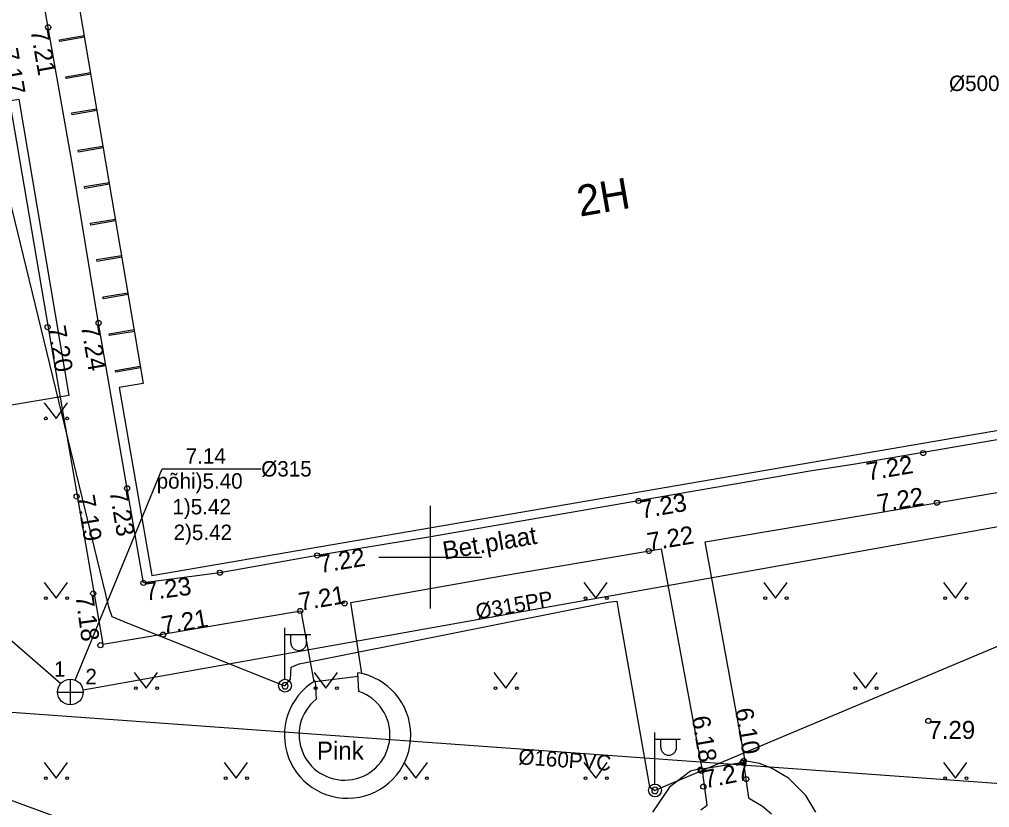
# Model space of a CAD drawing. Extents: x 473307 to 473719, y 6532843 to 6533381.
# Drawn here: x 473584.01 to 473621.77, y 6532940.25 to 6532970.93 of the extents above; entities that cross this region are included whole.
import ezdxf

# ---------------------------------------------------------------- set-up
doc = ezdxf.new("R2010")
doc.units = 0
for name, color, linetype in [('AED', 7, 'Continuous'), ('Default', 7, 'Continuous'), ('HALJASTUS', 7, 'Continuous'), ('HOONE', 7, 'Continuous'), ('HOONEDET', 7, 'Continuous'), ('KKAEV_NR', 7, 'Continuous'), ('KORGUS', 7, 'Continuous'), ('KTRASS', 7, 'Continuous'), ('KTRASS_TEKST', 7, 'Continuous'), ('MPKAABEL', 7, 'Continuous'), ('POST', 7, 'Continuous'), ('RAJATIS', 7, 'Continuous'), ('SKKAEV', 7, 'Continuous'), ('SKKAEV_NR', 7, 'Continuous'), ('SKTRASS', 7, 'Continuous'), ('SKTRASS_TEKST', 7, 'Continuous'), ('TEE', 7, 'Continuous'), ('VORK', 7, 'Continuous'), ('VTRASS', 7, 'Continuous')]:
    doc.layers.add(name, color=color, linetype=linetype)

# ---------------------------------------------------------------- blocks, each defined once
blk = doc.blocks.new('MURU')
at = {"layer": 'Default'}
for p, q in [((-0.927, 1.213), (0, 0)), ((0, 0), (0.891, 1.213))]:
    blk.add_line(p, q, dxfattribs=at)
for centre in [(-0.802, 0), (0.856, 0)]:
    blk.add_circle(centre, 0.11, dxfattribs=at)
blk = doc.blocks.new('MEPOST')
at = {"layer": 'Default'}
blk.add_circle((0, 0), 0.5, dxfattribs=at)
for start, end in [(0, 180), (180, 0)]:
    blk.add_arc((0, 0), 0.25, start, end, dxfattribs=at)
blk = doc.blocks.new('VAPOST')
at = {"layer": 'Default'}
for p, q in [((0, 0.5), (0, 4.5)), ((0, 4), (2, 4)), ((0.453, 3.358), (0.453, 4)), ((1.679, 3.358), (1.679, 4))]:
    blk.add_line(p, q, dxfattribs=at)
blk.add_arc((1.066, 3.358), 0.613, 180, 0, dxfattribs=at)
blk = doc.blocks.new('KAKAEV')
at = {"layer": 'Default'}
for p, q in [((0, -1), (0, 1)), ((-1, 0), (1, 0))]:
    blk.add_line(p, q, dxfattribs=at)
blk.add_circle((0, 0), 1, dxfattribs=at)
blk = doc.blocks.new('VKORIS')
at = {"layer": 'Default'}
for p, q in [((0, 4), (0, -4)), ((-4, 0), (4, 0))]:
    blk.add_line(p, q, dxfattribs=at)

msp = doc.modelspace()

# ---------------------------------------------------------------- linework, layer by layer
at = {"layer": 'AED'}
msp.add_lwpolyline([(473550.051, 6532959.211), (473554.174, 6532956.453), (473573.719, 6532945.513), (473580.254, 6532941.8), (473591.86, 6532937.524), (473605.919, 6532932.298), (473608.286, 6532931.42), (473621.231, 6532928.229), (473637.541, 6532925.082), (473652.528, 6532925.143), (473654.3, 6532926.84), (473651.933, 6532941.676), (473648.983, 6532959.55), (473630.652, 6532956.493)], dxfattribs=at)
at = {"layer": 'HOONE'}
msp.add_lwpolyline([(473585.831, 6533013.369), (473574.881, 6533011.486), (473566.132, 6533009.962), (473540.511, 6533005.576), (473543.395, 6532988.91), (473585.455, 6532976.623), (473588.828, 6532956.753), (473587.886, 6532956.595), (473589.164, 6532949.286), (473629.221, 6532956.166), (473626.335, 6532972.834), (473619.836, 6532974.765), (473602.305, 6532979.874), (473597.625, 6532979.18), (473590.334, 6532981.418), (473586.157, 6533005.917), (473587.084, 6533006.076)], close=True, dxfattribs=at)
at = {"layer": 'HOONEDET'}
for points in [[(473586.54, 6532970.231), (473585.585, 6532970.069), (473585.573, 6532970.138), (473586.529, 6532970.3)], [(473586.785, 6532968.791), (473585.831, 6532968.629), (473585.819, 6532968.698), (473586.773, 6532968.86)], [(473587.024, 6532967.381), (473586.061, 6532967.218), (473586.049, 6532967.287), (473587.012, 6532967.45)], [(473587.27, 6532965.93), (473586.307, 6532965.767), (473586.295, 6532965.836), (473587.259, 6532965.999)], [(473587.511, 6532964.514), (473586.548, 6532964.351), (473586.536, 6532964.42), (473587.499, 6532964.583)], [(473587.753, 6532963.086), (473586.793, 6532962.923), (473586.781, 6532962.992), (473587.742, 6532963.155)], [(473587.993, 6532961.674), (473587.03, 6532961.511), (473587.018, 6532961.58), (473587.981, 6532961.743)], [(473588.24, 6532960.22), (473587.274, 6532960.056), (473587.262, 6532960.125), (473588.228, 6532960.289)], [(473588.483, 6532958.786), (473587.509, 6532958.621), (473587.497, 6532958.69), (473588.471, 6532958.855)], [(473588.725, 6532957.363), (473587.759, 6532957.199), (473587.747, 6532957.268), (473588.713, 6532957.432)]]:
    msp.add_lwpolyline(points, dxfattribs=at)
at = {"layer": 'KORGUS'}
for centre in [(473585.127, 6532970.62), (473587.089, 6532959.111), (473585.106, 6532958.952), (473619.184, 6532954.05), (473588.198, 6532952.676), (473586.235, 6532952.361), (473608.106, 6532952.185), (473619.718, 6532952.115), (473595.6, 6532950.065), (473608.504, 6532950.235), (473591.811, 6532949.391), (473588.835, 6532948.995), (473586.881, 6532948.583), (473596.663, 6532948.199), (473594.939, 6532947.905), (473589.602, 6532946.984), (473587.16, 6532946.57), (473619.382, 6532943.624), (473612.195, 6532942.07), (473610.517, 6532941.729), (473610.556, 6532941.68), (473612.155, 6532942), (473612.295, 6532941.358), (473610.625, 6532941.068)]:
    msp.add_circle(centre, 0.1, dxfattribs=at)
at = {"layer": 'KTRASS'}
msp.add_lwpolyline([(473580.81, 6532944.172), (473634.611, 6532940.293)], dxfattribs=at)
at = {"layer": 'MPKAABEL'}
msp.add_lwpolyline([(473583.235, 6532965.46), (473587.471, 6532948.068), (473587.608, 6532947.693), (473588.068, 6532947.488), (473594.06, 6532945.091), (473594.344, 6532944.993), (473594.554, 6532945.243), (473594.585, 6532945.716), (473594.889, 6532945.847), (473606.922, 6532948.24), (473607.253, 6532948.279), (473607.325, 6532947.9), (473608.527, 6532941.06), (473608.741, 6532940.918), (473608.9, 6532940.995), (473624.459, 6532947.538)], dxfattribs=at)
at = {"layer": 'RAJATIS'}
for points in [[(473595.512, 6532945.177), (473595.554, 6532944.467)], [(473597.215, 6532944.766), (473597.182, 6532945.496)], [(473610.58, 6532941.781), (473610.129, 6532941.67), (473609.307, 6532941.041), (473608.644, 6532940.077)], [(473610.526, 6532940.163), (473610.774, 6532940.339), (473610.58, 6532941.781)], [(473615.001, 6532940.076), (473614.611, 6532940.724), (473613.937, 6532941.396), (473613.281, 6532941.789), (473612.812, 6532941.964), (473612.171, 6532942.089), (473612.387, 6532940.629), (473612.932, 6532940.3), (473613.281, 6532940.01)]]:
    msp.add_lwpolyline(points, dxfattribs=at)
for centre, radius, start, end in [((473596.78, 6532943.071), 2.459, 121.0435, 80.585), ((473596.66, 6532943.086), 1.769, 128.6894, 71.7199)]:
    msp.add_arc(centre, radius, start, end, dxfattribs=at)
at = {"layer": 'SKKAEV_NR'}
msp.add_lwpolyline([(473586.181, 6532945.211), (473589.565, 6532953.437), (473593.42, 6532953.437)], dxfattribs=at)
at = {"layer": 'SKTRASS'}
for points in [[(473573.77, 6532955.374), (473585.614, 6532945.077)], [(473586.483, 6532944.836), (473634.452, 6532953.395)]]:
    msp.add_lwpolyline(points, dxfattribs=at)
at = {"layer": 'TEE'}
for points in [[(473612.253, 6532942.073), (473610.701, 6532950.593), (473619.718, 6532952.115), (473624.689, 6532952.971), (473625.526, 6532947.885), (473627.22, 6532948.182), (473626.398, 6532953.295), (473631.923, 6532954.231), (473629.561, 6532967.499), (473628.117, 6532975.676)], [(473628.659, 6532961.442), (473629.682, 6532955.878), (473626.442, 6532955.32), (473616.532, 6532953.615), (473614.764, 6532953.342), (473608.106, 6532952.185), (473599.94, 6532950.776), (473595.6, 6532950.065), (473591.811, 6532949.391), (473588.835, 6532948.995), (473588.198, 6532952.676), (473587.089, 6532959.111), (473586.081, 6532965.174), (473584.393, 6532974.809)], [(473554.501, 6532969.707), (473570.029, 6532972.36), (473570.276, 6532972.512), (473570.673, 6532972.387), (473582.421, 6532974.587), (473583.816, 6532966.613), (473585.244, 6532958.249), (473587.257, 6532946.609), (473594.954, 6532947.911), (473595.461, 6532945.145)], [(473597.336, 6532945.465), (473596.906, 6532948.234), (473602.789, 6532949.269), (473608.985, 6532950.319), (473610.562, 6532941.776)], [(473595.513, 6532945.153), (473597.188, 6532945.365)], [(473610.583, 6532941.758), (473612.181, 6532942.019)]]:
    msp.add_lwpolyline(points, dxfattribs=at)
msp.add_arc((473662.369, 6533136.344), 211.861, 247.32056, 250.93503, dxfattribs=at)
at = {"layer": 'VTRASS'}
msp.add_lwpolyline([(473585.934, 6532956.295), (473583.47, 6532955.877), (473581.516, 6532967.408), (473583.98, 6532967.826)], close=True, dxfattribs=at)

# ---------------------------------------------------------------- block references
at = {"layer": 'HALJASTUS', "xscale": 0.5, "yscale": 0.5}
for p in [(473585.438, 6532955.399), (473585.438, 6532948.399), (473606.438, 6532948.399), (473613.438, 6532948.399), (473620.438, 6532948.399), (473588.938, 6532944.899), (473595.938, 6532944.899), (473602.938, 6532944.899), (473616.938, 6532944.899), (473585.438, 6532941.399), (473592.438, 6532941.399), (473599.438, 6532941.399), (473606.438, 6532941.399), (473620.438, 6532941.399)]:
    msp.add_blockref('MURU', p, dxfattribs=at)
at = {"layer": 'POST', "xscale": 0.5, "yscale": 0.5}
for name, p in [('VAPOST', (473594.344, 6532944.993)), ('MEPOST', (473594.344, 6532944.993)), ('VAPOST', (473608.741, 6532940.918)), ('MEPOST', (473608.741, 6532940.918))]:
    msp.add_blockref(name, p, dxfattribs=at)
at = {"layer": 'SKKAEV', "xscale": 0.5, "yscale": 0.5}
msp.add_blockref('KAKAEV', (473585.991, 6532944.749), dxfattribs=at)
at = {"layer": 'VORK', "xscale": 0.5, "yscale": 0.5}
msp.add_blockref('VKORIS', (473600, 6532950), dxfattribs=at)

# ---------------------------------------------------------------- texts
at = {"layer": 'HOONE'}
msp.add_text('2H', height=1.2, rotation=9.8418, dxfattribs=at).set_placement((473605.82, 6532963.248))
at = {"layer": 'KKAEV_NR'}
msp.add_text('%%C500', height=0.6, dxfattribs=at).set_placement((473620.188, 6532968.141))
at = {"layer": 'KORGUS'}
for s, rotation, p in [('7.21', 279.9359, (473584.437, 6532970.499)), ('7.17', 279.8658, (473583.251, 6532969.749)), ('7.20', 279.7201, (473585.106, 6532958.952)), ('7.24', 279.7782, (473586.399, 6532958.992)), ('7.22', 9.7454, (473617.036, 6532952.971)), ('7.19', 279.7032, (473586.235, 6532952.361)), ('7.23', 279.8178, (473587.508, 6532952.557)), ('7.23', 9.8582, (473608.226, 6532951.495)), ('7.22', 9.5808, (473617.45, 6532951.732)), ('7.22', 9.6631, (473608.504, 6532950.235)), ('7.22', 9.3038, (473595.713, 6532949.374)), ('7.23', 7.5795, (473588.927, 6532948.301)), ('7.21', 9.6778, (473594.939, 6532947.905)), ('7.18', 277.8909, (473586.188, 6532948.487)), ('7.21', 9.9365, (473589.602, 6532946.984)), ('6.10', 279.6631, (473611.854, 6532944.074)), ('6.18', 279.6631, (473610.17, 6532943.766)), ('7.27', 11.4871, (473610.695, 6532940.994))]:
    msp.add_text(s, height=0.7, rotation=rotation, dxfattribs=at).set_placement(p)
msp.add_text('7.29', height=0.7, dxfattribs=at).set_placement((473619.382, 6532942.924))
at = {"layer": 'KTRASS_TEKST'}
msp.add_text('%%C160PVC', height=0.6, rotation=355.8676, dxfattribs=at).set_placement((473603.411, 6532941.941))
at = {"layer": 'RAJATIS'}
msp.add_text('Pink', height=0.7, dxfattribs=at).set_placement((473595.587, 6532942.119))
at = {"layer": 'SKKAEV_NR'}
for s, p in [('7.14', (473590.479, 6532953.637)), ('%%C315', (473593.42, 6532953.137)), ('põhi)5.40', (473589.35, 6532952.664)), ('1)5.42', (473589.964, 6532951.664)), ('2)5.42', (473590.007, 6532950.664)), ('1', (473585.353, 6532945.341)), ('2', (473586.576, 6532945.052))]:
    msp.add_text(s, height=0.6, dxfattribs=at).set_placement(p)
at = {"layer": 'SKTRASS_TEKST'}
msp.add_text('%%C315PP', height=0.6, rotation=10.0343, dxfattribs=at).set_placement((473601.82, 6532947.575))
at = {"layer": 'TEE'}
msp.add_text('Bet.plaat', height=0.7, rotation=9.7454, dxfattribs=at).set_placement((473600.545, 6532949.899))

doc.saveas('drawing.dxf')
